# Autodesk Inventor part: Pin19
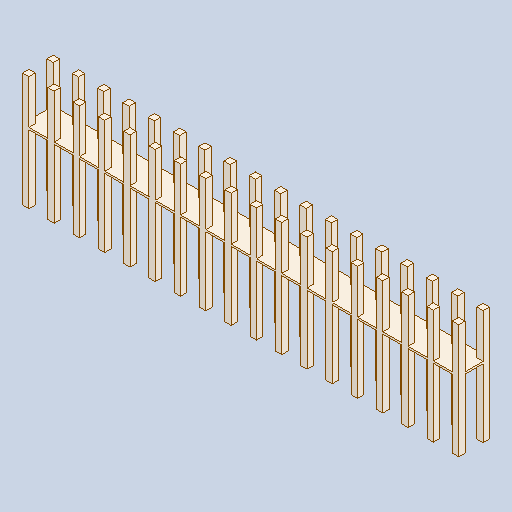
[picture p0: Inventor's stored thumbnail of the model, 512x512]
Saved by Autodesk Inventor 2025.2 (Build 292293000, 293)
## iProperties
Created: 2025-04
Part Number: Pin19
Material: Generic
Description: PART--DESC
Document SubType Name: Modeling
Designer: BennF
Density: 1 g/cm^3
Appearance: Default
Author: BennF
Revision Number: NONE
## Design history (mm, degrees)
feature "Solid"
body "Solid1"
